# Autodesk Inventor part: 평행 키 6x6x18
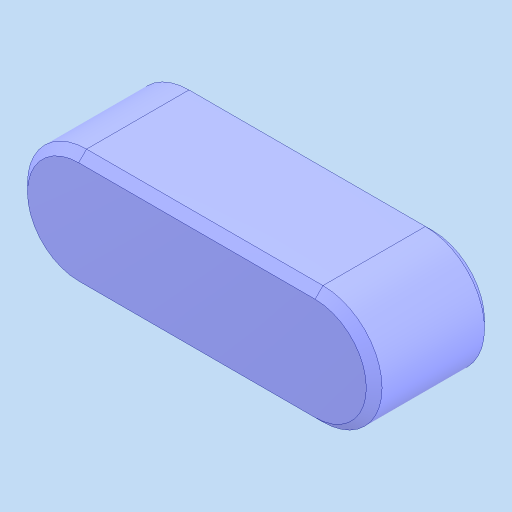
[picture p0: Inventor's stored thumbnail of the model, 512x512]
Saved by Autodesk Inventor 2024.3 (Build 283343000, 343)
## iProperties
Created: 2026-01
Part Number: 평행 키 6x6x18
Material: 강철, 연강
Description: 키 및 해당 키홈
Document SubType Name: Modeling
Designer: PC2-02
Density: 7.85 g/cm^3
Appearance: 기본값
Author: jhkim
Sending System: Autodesk Inventor 2026
Preprocessor: ST-DEVELOPER v20.1
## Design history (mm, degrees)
node "평행 키 6x6x181"
node "솔리드1"
body "Solid1"
